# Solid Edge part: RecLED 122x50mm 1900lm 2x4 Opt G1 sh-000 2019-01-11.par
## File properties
Author: lukasz.lemanski
Template: iso metric part.par
Last saved by: lukasz.lemanski
Revision: 1
Application: Solid Edge
Username: lukasz.lemanski
Gęstość: 0,000 kg/m^3
Dokładność: 0,990
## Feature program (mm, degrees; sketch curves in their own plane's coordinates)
body "unnamed Body 1"
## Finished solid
Body 1: solid body, 723 faces, 1859 edges, 1149 vertices.
  Faces by surface: plane 317, cylinder 256, spline 80, torus 27, cone 26, sphere 10, spun 7
  Edges by curve: line 1052, circle 383, curve on surface 282, ellipse 98, spline 38, intersection 6
Bounding box of the edges (mm; curved faces can reach further): 49.500 x 4.950 x 121.400, from (-24.75, -3.45, -60.7) to (24.75, 1.5, 60.7).
Cylindrical faces by radius (mm): R0.05 x32, R0.1 x96, R0.2 x47, R0.2002 x2, R0.2169 x3, R0.25 x12, R0.3 x2, R0.3373 x3, R0.4 x8, R0.4006 x2, R0.4008 x2, R0.525 x2, R0.6 x12, R1 x7, R1.05 x8, R1.0894 x2, R1.1 x14, R1.6 x2
Conical faces (half-angle, radius in mm at the cone's reference point): 0.5 deg R0.5056 x4, 0.5 deg R1.0082 x4, 1 deg R0.5511 x2, 10 deg R0.2132 x2, 10 deg R0.4132 x2, 18.4844 deg R1.0657 x4, 27.363 deg R0.6214 x2, 45 deg R0.575 x2, 45 deg R0.625 x4
Toroidal faces (ring radius, tube radius in mm): R-0.0731 r1.395 x8, R0.1 r0.2 x1, R0.8 r0.2 x4, R0.8522 r0.3 x2, R0.9002 r0.2 x1, R0.9018 r0.2 x1, R1.3 r0.2 x2, R1.4708 r0.15 x8
Spherical faces by radius (mm): R0.2 x8, R0.6 x2
Planar faces by outward normal: +x 45, +y 16, +z 41, -x 45, -y 28, -z 58, oblique 84
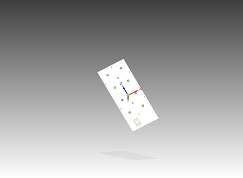
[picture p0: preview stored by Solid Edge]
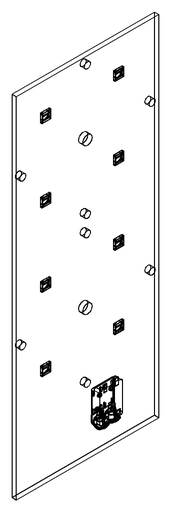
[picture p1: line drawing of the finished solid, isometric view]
